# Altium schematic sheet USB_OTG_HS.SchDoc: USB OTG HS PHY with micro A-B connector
size A4; Date: 29-OCT-2015; Author: A.B; CompanyName: STMicroelectronics; Organization: MCD/TOOLS/GNB; Address1: 12, Rue Jules HOROWITZ; Address2: 38019 Grenoble; Address3: FRANCE; DocumentNumber: MB1225; Revision: B-01; SheetNumber: 8; SheetTotal: 12; Project: STM32F769I-DISCO
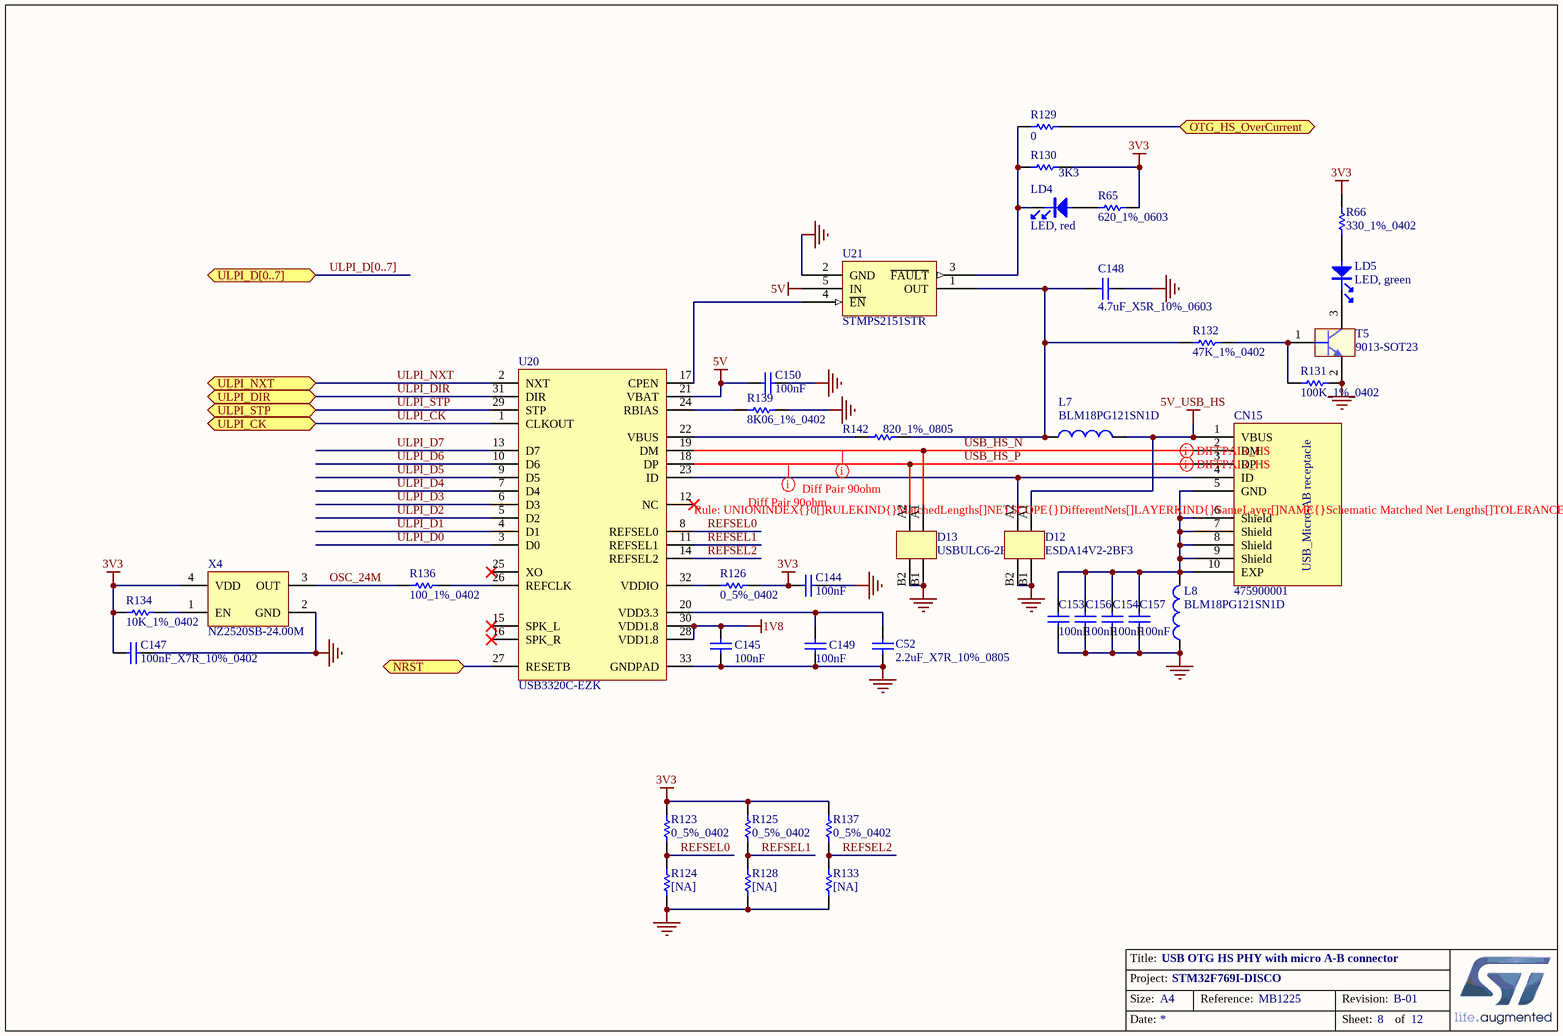
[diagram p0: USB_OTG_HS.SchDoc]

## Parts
C52  2.2uF_X7R_10%_0805  [TAN-A]
C144  100nF  [0402C]
C145  100nF  [0402C]
C147  100nF_X7R_10%_0402  [0402C]
C148  4.7uF_X5R_10%_0603  [0603C]
C149  100nF  [0402C]
C150  100nF  [0402C]
C153  100nF  [0402C]
C154  100nF  [0402C]
C156  100nF  [0402C]
C157  100nF  [0402C]
CN15  475900001  [MOLEX_47590001]
D12  ESDA14V2-2BF3  [BGA4_0R4_0R8X0R8]
D13  USBULC6-2F3  [BGA4_0R4_0R8X0R8]
L7  BLM18PG121SN1D  [0603L]
L8  BLM18PG121SN1D  [0603L]
LD4  LED, red  [0603D]
LD5  LED, green  [0603D]
R65  620_1%_0603  [0603R]
R66  330_1%_0402  [0402R]
R123  0_5%_0402  [0402R]
R124  [NA]  [0402R]
R125  0_5%_0402  [0402R]
R126  0_5%_0402  [0402R]
R128  [NA]  [0402R]
R129  0  [0402R]
R130  3K3  [0402R]
R131  100K_1%_0402  [0402R]
R132  47K_1%_0402  [0402R]
R133  [NA]  [0402R]
R134  10K_1%_0402  [0402R]
R136  100_1%_0402  [0402R]
R137  0_5%_0402  [0402R]
R139  8K06_1%_0402  [0402R]
R142  820_1%_0805  [0805R]
T5  9013-SOT23  [SOT-23]
U20  USB3320C-EZK  [QFN32_0R5_5X5]
U21  STMPS2151STR  [SOT23-5]
X4  NZ2520SB-24.00M  [OSC_4SM_2R5X2]

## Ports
NRST, OTG_HS_OverCurrent, ULPI_CK, ULPI_D[0..7], ULPI_DIR, ULPI_NXT, ULPI_STP

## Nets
1V8: C145.2 U20.28(VDD1.8) U20.30(VDD1.8)
3V3: C144.1 C147.1 R65.2 R66.2 R123.2 R125.2 R126.2 R130.1 R134.1 R137.2 X4.4(VDD)
5V: C150.1 U20.21(VBAT) U21.5(IN)
5V_USB_HS: CN15.1(VBUS) D12.A1 L7.2
GND: C52.1 C144.2 C145.1 C147.2 C148.2 C149.1 C150.2 C153.1 C154.1 C156.1 C157.1 D12.B1 D12.B2 D13.B1 D13.B2 L8.1 R124.1 R128.1 R131.2 R133.1 R139.2 T5.2(E) U20.33(GNDPAD) U21.2(GND) X4.2(GND)
NRST: U20.27(RESETB) ; port NRST
OSC_24M: R136.1 X4.3(OUT)
OTG_HS_OverCurrent: R129.2 ; port OTG_HS_OverCurrent
REFSEL0: R123.1 R124.2 U20.8(REFSEL0)
REFSEL1: R125.1 R128.2 U20.11(REFSEL1)
REFSEL2: R133.2 R137.1 U20.14(REFSEL2)
ULPI_CK: U20.1(CLKOUT) ; port ULPI_CK
ULPI_D0: U20.3(D0)
ULPI_D1: U20.4(D1)
ULPI_D2: U20.5(D2)
ULPI_D3: U20.6(D3)
ULPI_D4: U20.7(D4)
ULPI_D5: U20.9(D5)
ULPI_D6: U20.10(D6)
ULPI_D7: U20.13(D7)
ULPI_DIR: U20.31(DIR) ; port ULPI_DIR
ULPI_NXT: U20.2(NXT) ; port ULPI_NXT
ULPI_STP: U20.29(STP) ; port ULPI_STP
USB_HS_N: CN15.2(DM) D13.A1 U20.19(DM)
USB_HS_P: CN15.3(DP) D13.A2 U20.18(DP)
NetC52_2: C52.2 C149.2 U20.20(VDD3.3)
NetC148_1: C148.1 L7.1 R132.1 R142.2 U21.1(OUT)
NetC153_2: C153.2 C154.2 C156.2 C157.2 CN15.5(GND) CN15.6(Shield) CN15.7(Shield) CN15.8(Shield) CN15.9(Shield) CN15.10(EXP) L8.2
NetCN15_4: CN15.4(ID) D12.A2 U20.23(ID)
NetLD4_1: LD4.1 R65.1
NetLD4_2: LD4.2 R129.1 R130.2 U21.3(~{FAULT})
NetLD5_1: LD5.1 R66.1
NetLD5_2: LD5.2 T5.3(C)
NetR126_1: R126.1 U20.32(VDDIO)
NetR131_1: R131.1 R132.2 T5.1(B)
NetR134_2: R134.2 X4.1(EN)
NetR136_2: R136.2 U20.26(REFCLK)
NetR139_1: R139.1 U20.24(RBIAS)
NetR142_1: R142.1 U20.22(VBUS)
NetU20_17: U20.17(CPEN) U21.4(~{EN})

Not connected (* = marked no-connect by the designer): U20 12(NC)* 15(SPK_L)* 16(SPK_R)* 25(XO)*

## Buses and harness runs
bus ULPI_D[0..7] = port ULPI_D[0..7]

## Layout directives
differential pair: USB_HS_N, USB_HS_P
rule Matched Net Lengths [Tolerance = 150mil]: USB_HS_N, USB_HS_P

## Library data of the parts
C52 = Cap_2.2uF_X7R_10%_0805: Capacitor,2.2uF,16V, X7R,10%,0805,YAGEO; Manuf_Part_1: CC0805KKX7R7BB225
C144 C145 C147 C149 C150 C153 C154 C156 C157 = Cap_100nF_X7R_10%_0402: Capacitor,100nF,16V,X7R,10%,0402,YAGEO; Manuf_Part_1: CC0402KRX7R7BB104
C148 = Cap_4.7uF_X5R_10%_0603: Capacitor,4.7uF,16V, X5R,10%,0603,YAGEO; Manuf_Part_1: CC0603KRX5R7BB475; Order: CC0603KRX5R7BB105
CN15 = 475900001: USB-MICRO-AB, 47590-0001, SMT, MOLEX
D12 = ESDA14V2-2BF3: Quad bidirectional Transil array for ESD protection; Manuf_1: STM; ECCN_US/EU: EAR99/NEC; Provided: ST; Ref St: 9179040
D13 = USBULC6-2F3: 2-line Transil, (TVS), ultralow capacitance protection for high speed USB; Manuf_1: STM; ECCN_US/EU: EAR99/NEC; Ref St: 9151090; Provided: ST
L7 L8 = BEAD_120R_2A_0603: Bead,120R,2A,0603,BLM18PG121SN1D,MURATA; Manuf_Part_3: FCM1608KF-601T03; Manuf_2: TDK; Manuf_Part_2: MPZ1608S300A; Manuf_3: Tai-tech; Value: 100uH; Description_3: Bead,600R,350mA,0603,FCM1608KF-601T03,Tai-tech; Description_2: Bead,30R,5A,0603,MPZ1608S300A,TDK
LD4 = LED_red: LED, red, 0603; Manuf_1: everlight; Manuf_Part_1: 19-213-R6C-AP1Q2B/3T; Description: LED,red,0603,19-213-R6C-AP1Q2B/3T,everlight; ECCN_US/EU: EAR99/NEC
LD5 = LED_green: LED, green, 0603; Manuf_1: everlight; Manuf_Part_1: 19-213SYGC/S530-E2/TR8; Description: LED,green,0603,19-213SYGC/S530-E2/TR8,everlight; ECCN_US/EU: EAR99/NEC
R65 = Res_620_1%_0603: Resistor,620,0603,1%,VISHAY; Manuf_Part_1: CRCW0603620RFKEA; Manuf_1: VISHAY DRALORIC; Value: 620; Order: 2122341
R66 = Res_330_1%_0402: Resistor,330,0402,1%,YAGEO; Manuf_Part_1: RC0402FR-07330RL; Value: 330
R123 R125 R126 R137 = Res_0_5%_0402: Resistor,0,0402,5%,YAGEO; Manuf_Part_1: RC0402JR-070RL; Value: 0; Order: 2363467
R124 R128 R133 = Res_NA_0402: Resistor,[NA],0402; Fitted: NO
R129 = Res_0_5%_0402: Resistor,0,0402,5%,YAGEO; Manuf_Part_1: RC0402JR-070RL; Order: 2363467
R130 = Res_3K3_1%_0402: Resistor,3K3,0402,1%,YAGEO; Manuf_Part_1: RC0402FR-073K3L
R131 = Res_100K_1%_0402: Resistor,100K,0402,1%,YAGEO; Manuf_Part_1: RC0402FR-07100KL; Manuf_Part_2: RT0402FRE07100KL
R132 = Res_47K_1%_0402: Resistor,47K,0402,1%,YAGEO; Manuf_Part_1: RC0402FR-0747KL; Order: 9239430
R134 = Res_10K_1%_0402: Resistor,10K,0402,1%,YAGEO; Manuf_Part_1: RC0402FR-0710KL
R136 = Res_100_1%_0402: Resistor,100,0402,1%,YAGEO; Manuf_Part_1: RC0402FR-07100RL; Value: 100; Order: 9239111
R139 = Res_8K06_1%_0402: Resistor,8K06,0402,1%,YAGEO; Manuf_Part_1: RC0402FR-078K06L
R142 = Res_820_1%_0805: Resistor,820,0805,1%,YAGEO; Manuf_Part_1: RC0805FR-07820RL; Value: 820
T5 = 9013-SOT23: NPN Bipolar Transistor; Manuf_1: NXP; Manuf_Part_1: BSR14; Description: NPN Bipolar Transistor, SOT-23 Footprint; Order: 1081310; ECCN_US/EU: EAR99/NEC
U20 = USB3320C-EZK: USB3320C,  Hi-Speed USB Host, Device or OTG PHY with ULPI Low Pin Interface; Manuf_1: MICROCHIP; Manuf_Part_1: USB3320C-EZK-TR; ECCN_US/EU: EAR99/NEC; Provided: Sub Co
U21 = STMPS2151STR: Enhanced single channel power switches; Manuf_1: STM; Provided: ST; ECCN_US/EU: EAR99/NEC; Ref St: xxxxxx
X4 = OSC_24M_NZ2520SB: Oscillator 24.00Mhz, -+50PPM, 3.3V, Temp -55 to +125°C; Manuf_Part_2: KC2520B24.0000C10E00; Manuf_1: NDK; Manuf_Part_1: NZ2520SB 24MHz END4869A; Manuf_2: AVX Corp/Kyocera Corp; ECCN_US/EU: EAR99/NEC; Ref St: 9157032; Provided: ST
